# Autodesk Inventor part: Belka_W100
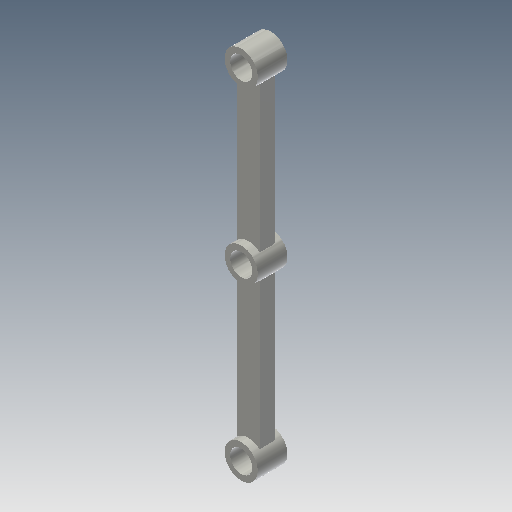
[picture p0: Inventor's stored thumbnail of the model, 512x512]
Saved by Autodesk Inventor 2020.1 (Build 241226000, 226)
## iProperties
Created: 2005-10
Part Number: Belka_W100
Document SubType Name: Modeling
Designer: F.Stasiak
Density: 1 g/cm^3
Material: Ogólny
Appearance: Gładkie — w kolorze kości słoniowej
Manager: www.cadconsulting.pl
Company: Fabian Stasiak CAD Consulting
Author: F.Stasiak
Subject: Zbiór ćwiczeń. Autodesk Inventor 2020. Kurs podstawowy
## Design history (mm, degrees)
sketch "Szkic1"
  geometry: L1 (-15, 0)-(-15, 46); L2 (-18, 0)-(-18, 46); L3 (-12, 46)-(-12, 0); L4 (-15, 0)-(-15, -46); L5 (-18, 0)-(-18, -46); L6 (-12, 0)-(-12, -46); C1 r 4.5 at (-15, 0); C2 r 4.5 at (-15, 46); C3 r 4.5 at (-15, -46); A1 r 3 centre (-15, 0) between (-18, 0) and (-12, 0) reference; A2 r 3 centre (-15, 0) between (-18, 0) and (-12, 0); A3 r 3 centre (-15, 46) between (-18, 46) and (-12, 46); A4 r 3 centre (-15, -46) between (-18, -46) and (-12, -46)
  constraints: 12 end point, 8 point on circle, 6 centre point, 5 coincident, 5 equal radius, 5 tangent, 2 parallel, 1 vertical
  dimensions: "d9" = 9 diameter of C1; "d10" = 46 distance of L1.start L1.end; "d11" = 46 distance of L1.start L4.end (= d10)
  node "Odniesienie1"
extrude "Wyciągnięcie proste1" new body sketch "Szkic1" stored distance "d12" = 8; taper "d13" = 0 deg
extrude "Wyciągnięcie proste2" join sketch "Szkic1" stored distance "d14" = 4; taper "d15" = 0 deg
node "Bryła1"
node "Korpusy bryłowe"
node "Korpusy powierzchniowe"
